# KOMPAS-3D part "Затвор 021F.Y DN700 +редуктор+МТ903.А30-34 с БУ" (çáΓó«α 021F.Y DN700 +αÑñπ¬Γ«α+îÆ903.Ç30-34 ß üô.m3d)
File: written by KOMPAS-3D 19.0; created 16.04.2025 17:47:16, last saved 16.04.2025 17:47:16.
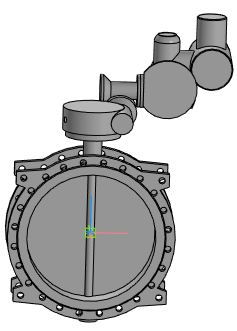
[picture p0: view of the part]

Document properties: Полное имя файла: Затвор 021F.Y DN700 +редуктор+МТ903.А30-34 с БУ.a3d

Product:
- Part/product: Затвор 021F.Y DN700 +редуктор+МТ903.А30-34 с БУ
    Масса: 767.863

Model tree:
1. Операция без истории:1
